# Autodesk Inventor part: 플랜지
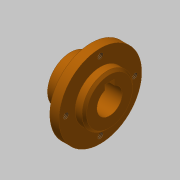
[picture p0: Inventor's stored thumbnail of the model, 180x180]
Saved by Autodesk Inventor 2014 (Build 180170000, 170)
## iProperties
Created: 2019-10
Part Number: 플랜지
Material: 스테인리스강
Document SubType Name: Modeling
Designer: mduedu
Density: 1 g/cm^3
Appearance: Orange
Author: mduedu
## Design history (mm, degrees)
sketch "스케치1"
  geometry: L1 (0, 0)-(9, 0); L2 (9, 0)-(9, 10); L3 (9, 10)-(0, 10); L4 (0, 10)-(0, 0); L5 (9, 0)-(13, 0); L6 (13, 0)-(13, 18); L7 (13, 18)-(9, 18); L8 (9, 18)-(9, 0); L9 (13, 0)-(17, 0); L10 (17, 0)-(17, 11); L11 (17, 11)-(13, 11); L12 (13, 11)-(13, 0)
  constraints: 24 end point, 6 parallel, 3 horizontal, 3 perpendicular
  dimensions: "d0" = 17 distance between parallel lines of L10 L4; "d2" = 20 diameter of L3 L1; "d3" = 22 diameter of L11 L9; "d4" = 36 diameter of L7 L5; "d5" = 4 distance of L6.end L7.end; "d6" = 4 distance of L10.end L11.end
revolve "회전1" sketch "스케치1" stored, may be unused: angle "d7" = 90 deg
sketch "스케치2"
  geometry: L1 (-2, 5.123)-(2, 5.123); L2 (2, 5.123)-(2, 7.3); L3 (2, 7.3)-(-2, 7.3); L4 (-2, 7.3)-(-2, 5.123); A1 r 5.5 centre (0, 0) between (-2, 5.123) and (2, 5.123); 1 further point
  constraints: 8 end point, 2 parallel, 2 point on circle, 1 centre point, 1 coincident, 1 horizontal, 1 perpendicular
  dimensions: "d8" = 11 diameter of A1; "d10" = 4 distance of L2.end L3.end; "d11" = 7.3 distance from line of L3 point (0, 0)
extrude "돌출1" cut sketch "스케치2" stored distance "d12" = 10; taper "d13" = 0 deg
chamfer "모따기1" distance "d14" = 1; stored, may be unused: second distance "d15" = 2, angle "d16" = 45 deg
chamfer "모따기2" distance "d17" = 1; stored, may be unused: second distance "d18" = 2, angle "d19" = 45 deg
sketch "스케치3" dims "d20" = 30
  geometry: 3 further points
  constraints: 2 vertical alignment, 1 coincident, 2 other
hole "구멍1" sketch "스케치3" at (0, 15) diameter "d21" = 2.459; stored, may be unused: countersink angle "d25" = 90 deg, drill point angle "d27" = 118 deg; dims "d22" = 6, "d23" = 4, "d24" = 2, "d26" = 8
node "솔리드1"
pattern_circular "원형 패턴1" dims angle "d29" = 360 deg
